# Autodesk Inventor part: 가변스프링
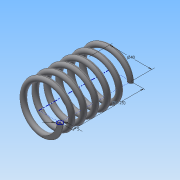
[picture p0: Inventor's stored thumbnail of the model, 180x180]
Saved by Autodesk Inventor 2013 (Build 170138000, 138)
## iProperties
Created: 2016-08
Part Number: 가변스프링
Material: 일반
Document SubType Name: Modeling
Designer: Administrator
Density: 1 g/cm^3
Author: Administrator
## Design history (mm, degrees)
sketch "스케치1"
  geometry: L1 (0, 0)-(20, 0); L2 (20, 0)-(20, 67.25); L3 (20, 67.25)-(0, 67.25); L4 (0, 67.25)-(0, 0); C1 r 2.5 at (20, 0)
  constraints: 8 end point, 2 parallel, 1 centre point, 1 coincident, 1 horizontal, 1 perpendicular
  dimensions: "d0" = 67.25 distance of L1.end L2.end (derived); "d2" = 40 diameter of L2 L4; "d3" = 5 diameter of C1
feature "코일1" pitch "d4" = 10; turns "d6" = 6; dims "d5" = 67.25 (= d0), "d7" = 0, angle "d8" = 90 deg, angle "d9" = 90 deg, "d10" = 0, "d11" = 0
sketch "스케치2"
  geometry: L1 (-22.5, 0)-(-17.5, 0) reference; L2 (-22.5, 0)-(-17.5, 0) reference; 1 further point
  constraints: 2 horizontal alignment
extrude "돌출1" cut sketch "스케치2" distance "d12" = 10; taper "d13" = 0 deg
node "작업 평면1"
sketch "스케치3"
  geometry: L1 (22.5, 0)-(17.5, 0) reference; 1 further point
  constraints: 1 horizontal alignment
extrude "돌출2" cut sketch "스케치3" distance "d14" = 10; taper "d15" = 0 deg
node "솔리드1"
node "절단 모서리 투영1"
node "절단 모서리 투영2"
node "절단 모서리 투영3"
